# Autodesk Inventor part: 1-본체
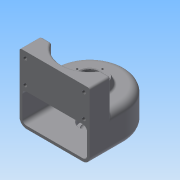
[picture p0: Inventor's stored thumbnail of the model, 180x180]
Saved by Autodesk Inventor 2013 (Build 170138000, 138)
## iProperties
Created: 2015-02
Part Number: 1-본체
Material: 일반
Document SubType Name: Modeling
Designer: Administrator
Density: 1 g/cm^3
Author: Administrator
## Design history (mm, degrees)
sketch "스케치1"
  geometry: L1 (-50, 0)-(-50, -50); L2 (-50, -50)-(50, -50); L3 (50, -50)-(50, 0); A1 r 50 centre (0, 0) between (-50, 0) and (50, 0); 1 further point
  constraints: 6 end point, 2 perpendicular, 2 point on circle, 1 centre point, 1 coincident, 1 tangent, 1 vertical
  dimensions: "d0" = 100 diameter of A1; "d2" = 50 distance from line of point (0, 0) L2; "d3" = 100 distance of L1.end L2.end
extrude "돌출1" new body sketch "스케치1" distance "d4" = 50; taper "d5" = 0 deg
fillet "모깎기1" dims "d6" = 10
feature "쉘1" dims "d7" = 4
node "작업 평면1"
sketch "스케치2"
  geometry: L1 (50, -50)-(40, -50) reference; L2 (40, -50)-(-40, -50) reference; L3 (-40, -50)-(-50, -50) reference; L4 (-50, -50)-(50, -50); L5 (50, -20)-(50, -50); L6 (-50, -20)-(-50, -50); L7 (50, 0)-(50, -50) reference; L8 (-50, -50)-(-50, 0) reference; L9 (50, -20)-(34.641, -20); L10 (-34.641, -20)-(-50, -20); A1 r 40 centre (0, 0) between (-34.641, -20) and (34.641, -20); 3 further points
  constraints: 10 end point, 4 collinear, 2 point on circle, 2 vertical alignment, 1 centre point, 1 coincident, 1 midpoint, 1 parallel, 1 point on line
  dimensions: "d9" = 80 diameter of A1; "d12" = 30 distance between parallel lines of L2 L9
extrude "돌출2" join sketch "스케치2" stored distance "d13" = 50; taper "d14" = 0 deg
sketch "스케치3"
  geometry: C1 r 25 at (0, 0); A1 r 40 centre (0, 0) between (-34.641, -20) and (34.641, -20) reference
  constraints: 1 centre point, 1 coincident
  dimensions: "d15" = 50 diameter of C1
extrude "돌출3" join sketch "스케치3" distance "d17" = 10; taper "d18" = -20 deg
hole "구멍1" diameter "d21" = 20; stored, may be unused: countersink angle "d25" = 90 deg, drill point angle "d27" = 0 deg; dims "d19" = 10, "d20" = 10, "d22" = 6, "d23" = 28, "d24" = 10, "d26" = 14
sketch "스케치4"
  geometry: C1 r 14 at (0, 0) reference; C2 r 21.36 at (0, 0) reference; A1 r 18 centre (0, 0) between (0, 18) and (0, -18); 2 further points
  constraints: 4 point on circle, 2 coincident, 2 horizontal alignment, 2 vertical alignment, 1 centre point
  dimensions: "d28" = 36 diameter of A1
hole "구멍2" sketch "스케치4" at (0, 18), (0, -18), (18, 0), (-18, 0) diameter "d30" = 2.459; stored, may be unused: countersink angle "d34" = 90 deg, drill point angle "d36" = 118 deg; dims "d31" = 6, "d32" = 28, "d33" = 10, "d35" = 9
sketch "스케치5"
  geometry: C1 r 20 at (0, 0); A1 r 40 centre (0, 0) between (40, 0) and (-40, 0) reference
  constraints: 1 centre point, 1 coincident
  dimensions: "d37" = 40 diameter of C1
extrude "돌출4" join sketch "스케치5" distance "d39" = 9; taper "d40" = 0 deg
hole "구멍3" diameter "d43" = 20; stored, may be unused: countersink angle "d47" = 90 deg, drill point angle "d49" = 0 deg; dims "d41" = 10, "d42" = 10, "d44" = 6, "d45" = 28, "d46" = 8, "d48" = 10
sketch "스케치6"
  geometry: L1 (90, 95)-(-10, 95) reference; L2 (-1.75, 53)-(81.75, 53); L3 (81.75, 53)-(81.75, 86); L4 (81.75, 86)-(-1.75, 86); L5 (-1.75, 86)-(-1.75, 53); 7 further points
  constraints: 8 end point, 4 coincident, 2 midpoint, 2 parallel, 1 horizontal, 1 perpendicular, 1 vertical alignment
  dimensions: "d50" = 9 distance between parallel lines of L4 L1; "d51" = 33 distance of L2.end L3.end; "d52" = 83.5 distance of L3.end L4.end
hole "구멍4" sketch "스케치6" at (-1.75, 86), (-1.75, 53), (81.75, 53), (81.75, 86) diameter "d53" = 5.134; stored, may be unused: countersink angle "d57" = 90 deg, drill point angle "d59" = 118 deg; dims "d54" = 10, "d55" = 28, "d56" = 8, "d58" = 13
chamfer "모따기1" distance "d60" = 1; stored, may be unused: second distance "d61" = 2, angle "d62" = 45 deg
fillet "모깎기2" dims "d63" = 0.3, "d64" = 3
node "작업 평면2"
sketch "스케치7"
  geometry: L1 (40, 0)-(-40, 0) reference; 2 further points
  constraints: 1 vertical alignment, 1 other
  dimensions: "d65" = 25 distance from line of point (0, 25) L1
feature "엠보싱1" sketch "스케치7" dims "d9" = 80, "d12" = 30, "d66" = 0.5, "d67" = 0
node "솔리드1"
other parameters: "d8" = -95
